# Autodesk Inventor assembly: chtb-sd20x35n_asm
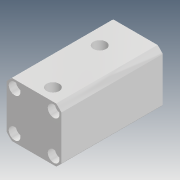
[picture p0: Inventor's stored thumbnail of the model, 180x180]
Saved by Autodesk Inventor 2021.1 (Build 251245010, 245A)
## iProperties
Company: Microsoft
Created: 2018-04
Part Number: chtb-sd20x35n_asm
Description: STEP AP214
Document SubType Name: Assembly
Designer: user
Title: chtb-sd20x35n_asm.STEP
Author: Windows
Revision Number: ÈÎºÎ
Sending System: SolidWorks 2015
Preprocessor: SwSTEP 2.0
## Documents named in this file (4)
- D:\Vault_2016\Projekty\Clamptek\Hydraulic\CHTB\CHTB-20\Inventor\CHTB-SD20x35N\chtb-sd20x35n_asm.iam
- D:\Vault_2016\Projekty\Clamptek\Hydraulic\CHTB\CHTB-20\Inventor\CHTB-SD20x35N\CHTB-SD20X35NBT.ipt
- D:\Vault_2016\Projekty\Clamptek\Hydraulic\CHTB\CHTB-20\Inventor\CHTB-SD20x35N\CHTB-SD20X35NHSG.ipt
- D:\Vault_2016\Projekty\Clamptek\Hydraulic\CHTB\CHTB-20\Inventor\CHTB-SD20x35N\QG.ipt
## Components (3 placed, 3 different names)
1. CHTB-SD20X35NBT_1
2. CHTB-SD20X35NHSG_2
3. QG_3
